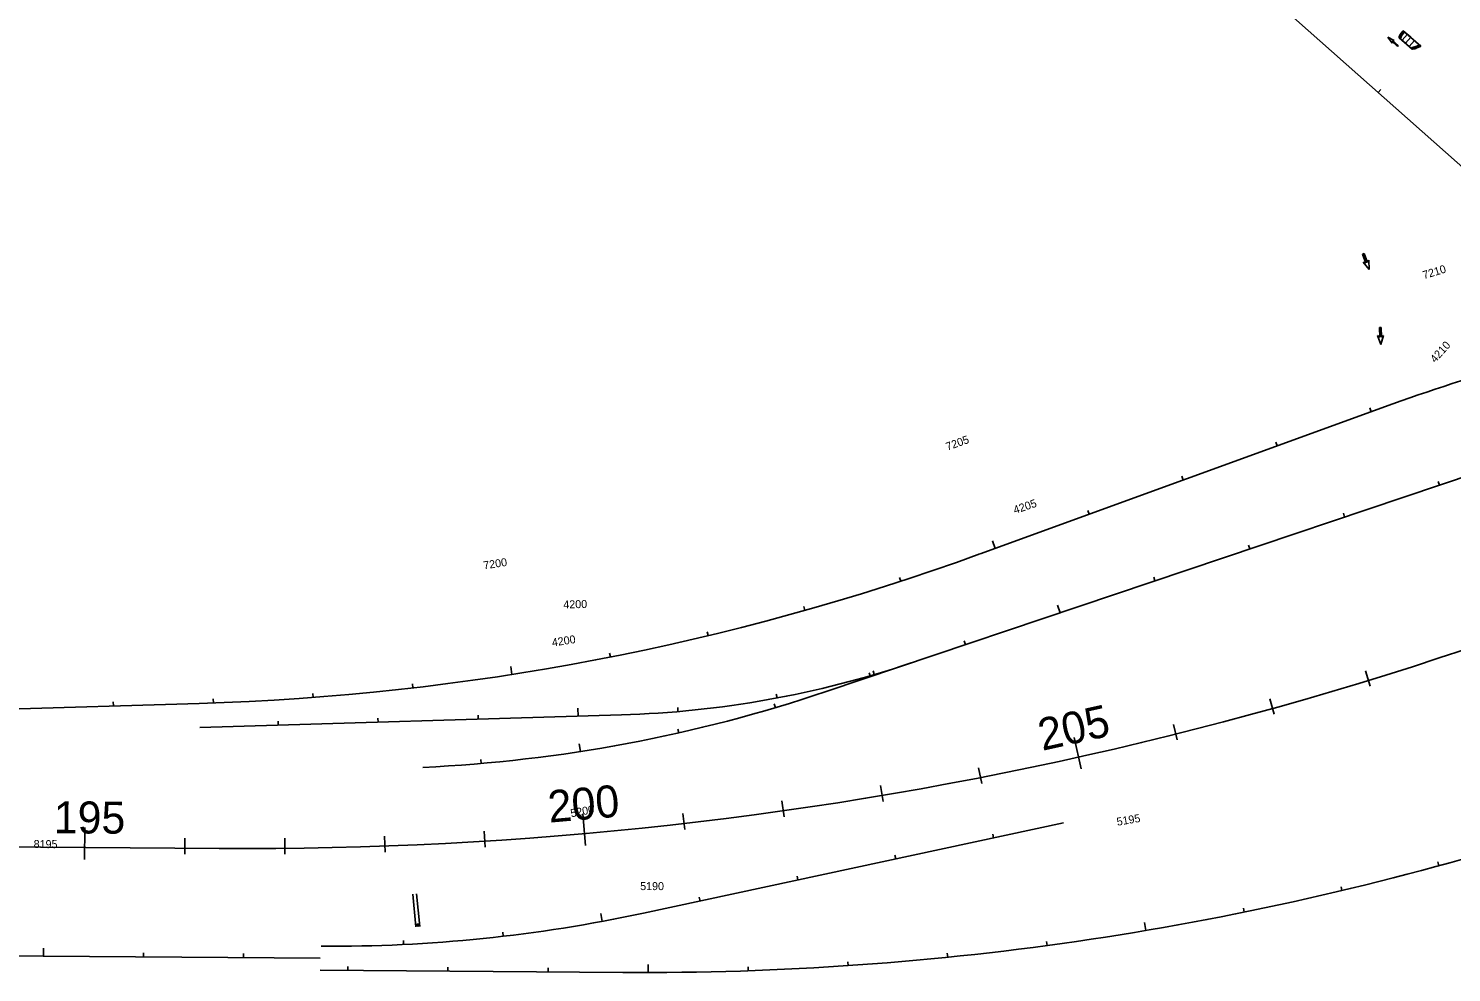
# Model space of a CAD drawing. Extents: x -5665 to 1997148, y 4 to 827579.
# Drawn here: x 1969802 to 1971224, y 802183 to 803127 of the extents above; entities that cross this region are included whole.
import ezdxf

# ---------------------------------------------------------------- set-up
doc = ezdxf.new("R2010")
doc.units = 0
for name, color, linetype in [('RD_EX_BldgApp', 7, 'Continuous'), ('RD_HC_CL_Rel', 7, 'Continuous'), ('RD_HC_Data_Tic_Rel', 7, 'Continuous'), ('RD_HC_TX_Rel_Sta50', 7, 'Continuous'), ('RD_PD_SW', 7, 'Continuous'), ('RD_Sketch8', 7, 'Continuous')]:
    doc.layers.add(name, color=color, linetype=linetype)

msp = doc.modelspace()

# ---------------------------------------------------------------- linework, layer by layer
at = {"layer": 'RD_EX_BldgApp'}
for p, q in [((1970186.2, 802261.1), (1970189.2, 802228.4)), ((1970192.9, 802228.6), (1970189.6, 802261.4))]:
    msp.add_line(p, q, dxfattribs=at)
for points in [[(1970190.5, 802229.4), (1970191.1, 802229.2), (1970191.6, 802229.4), (1970192, 802229.8), (1970192.1, 802230.4), (1970191.8, 802230.9), (1970191.4, 802231.2), (1970190.8, 802231.2), (1970190.3, 802231), (1970190.1, 802230.5), (1970190.1, 802229.9), (1970190.4, 802229.4), (1970190.5, 802229.4)], [(1970190.6, 802229.6), (1970191.1, 802229.4), (1970191.6, 802229.6), (1970191.8, 802230), (1970191.8, 802230.5), (1970191.5, 802230.9), (1970191, 802231.1), (1970190.5, 802230.9), (1970190.3, 802230.4), (1970190.3, 802229.9), (1970190.6, 802229.6)], [(1970190.7, 802229.7), (1970191.2, 802229.6), (1970191.5, 802229.9), (1970191.7, 802230.3), (1970191.5, 802230.7), (1970191.1, 802230.8), (1970190.7, 802230.7), (1970190.5, 802230.4), (1970190.5, 802229.9), (1970190.7, 802229.7)], [(1970190.8, 802229.9), (1970191.2, 802229.9), (1970191.4, 802230.1), (1970191.4, 802230.5), (1970191.1, 802230.6), (1970190.8, 802230.5), (1970190.7, 802230.2), (1970190.8, 802229.9), (1970190.8, 802229.9)], [(1970191, 802230.1), (1970191.2, 802230.1), (1970191.2, 802230.3), (1970191, 802230.4), (1970190.9, 802230.3), (1970191, 802230.1)]]:
    msp.add_lwpolyline(points, dxfattribs=at)
at = {"layer": 'RD_HC_CL_Rel'}
for p, q in [((1970807.3, 803367.7), (1971858, 802435.1)), ((1970753, 802601.3), (1971165.5, 802751.3)), ((1970599.2, 802463.6), (1971248.9, 802682.4)), ((1968911.4, 802420.4), (1969972.6, 802451.8)), ((1969973.3, 802427.8), (1970394.5, 802440.3)), ((1970416.5, 802242), (1970836.6, 802332.4)), ((1969096.7, 802313.5), (1969992.4, 802306.8)), ((1969095.9, 802204.5), (1970093.4, 802197)), ((1970093.3, 802185), (1970396, 802182.8))]:
    msp.add_line(p, q, dxfattribs=at)
for centre, radius, start, end in [((1971678.2, 801341.6), 1500, 99.0087, 109.9838), ((1970020.9, 806126.4), 3819.7, 269.5721, 296.6408), ((1969898.6, 804950.7), 2500, 271.6958, 289.9838), ((1970364.9, 803439.9), 1000, 271.6958, 288.6146), ((1970126.8, 803866.2), 1480, 272.6826, 288.6146), ((1970418.4, 805182.7), 3000, 269.5721, 287.5154), ((1970105.4, 803689), 1480, 269.5721, 282.1339)]:
    msp.add_arc(centre, radius, start, end, dxfattribs=at)
at = {"layer": 'RD_HC_Data_Tic_Rel'}
for p, q in [((1971151, 803062.6), (1971153.7, 803065.6)), ((1971144.1, 802743.5), (1971142.7, 802747.2)), ((1971050.1, 802709.3), (1971048.7, 802713)), ((1970956.1, 802675.1), (1970954.7, 802678.9)), ((1971212.2, 802670), (1971210.9, 802673.8)), ((1970862.1, 802640.9), (1970860.8, 802644.7)), ((1971117.4, 802638.1), (1971116.2, 802641.9)), ((1970768.1, 802606.8), (1970765.4, 802614.3)), ((1971022.7, 802606.2), (1971021.4, 802610)), ((1970673.7, 802573.9), (1970672.5, 802577.7)), ((1970927.9, 802574.3), (1970926.6, 802578.1)), ((1970833.1, 802542.4), (1970830.6, 802549.9)), ((1970578, 802544.8), (1970576.9, 802548.7)), ((1970481.3, 802519.6), (1970480.3, 802523.5)), ((1970738.4, 802510.4), (1970737.1, 802514.2)), ((1970383.6, 802498.2), (1970382.8, 802502.1)), ((1970285.1, 802480.8), (1970283.9, 802488.7)), ((1970643.6, 802478.5), (1970642.3, 802482.3)), ((1970647.3, 802480.6), (1970646.2, 802484.4)), ((1971143.1, 802469), (1971138.4, 802484.3)), ((1970186, 802467.3), (1970185.6, 802471.3)), ((1969886.7, 802449.3), (1969886.6, 802453.3)), ((1969986.7, 802452.3), (1969986.5, 802456.3)), ((1970086.5, 802457.8), (1970086.2, 802461.8)), ((1970548.5, 802447.5), (1970547.4, 802451.4)), ((1970550.2, 802457.2), (1970549.4, 802461.1)), ((1971047, 802440.9), (1971042.7, 802456.3)), ((1970151.3, 802433.1), (1970151.2, 802437.1)), ((1970251.3, 802436.1), (1970251.2, 802440.1)), ((1970351.2, 802439), (1970351, 802447)), ((1970451.1, 802443.6), (1970450.8, 802447.6)), ((1970051.4, 802430.1), (1970051.3, 802434.1)), ((1970451.8, 802422.3), (1970450.9, 802426.2)), ((1970950.2, 802415.3), (1970946.3, 802430.8)), ((1970353.6, 802403.6), (1970352.3, 802411.5)), ((1970854, 802386.3), (1970847.1, 802417.6)), ((1970254.3, 802391.7), (1970254, 802395.6)), ((1970754.7, 802371.7), (1970751.6, 802387.4)), ((1970656.1, 802353.8), (1970653.5, 802369.6)), ((1970557.2, 802338.4), (1970554.9, 802354.3)), ((1970358.7, 802309.6), (1970355.9, 802341.5)), ((1970457.8, 802325.7), (1970456, 802341.6)), ((1969858, 802295.8), (1969858.3, 802327.8)), ((1970258.3, 802308.1), (1970257.3, 802324)), ((1969958.1, 802301), (1969958.2, 802317)), ((1970058.2, 802300.9), (1970058, 802316.9)), ((1970158.3, 802303.1), (1970157.7, 802319.1)), ((1970766.5, 802317.3), (1970765.7, 802321.2)), ((1970668.7, 802296.3), (1970667.9, 802300.2)), ((1971211.7, 802289.5), (1971210.6, 802293.3)), ((1970571, 802275.3), (1970570.1, 802279.2)), ((1971114.8, 802264.6), (1971113.9, 802268.5)), ((1970473.2, 802254.2), (1970472.4, 802258.2)), ((1970375.3, 802233.8), (1970373.9, 802241.7)), ((1971017.2, 802243), (1971016.4, 802247)), ((1970276.4, 802218.9), (1970276, 802222.9)), ((1970918.9, 802224.7), (1970917.5, 802232.6)), ((1970176.8, 802210.7), (1970176.6, 802214.7)), ((1970820, 802209.7), (1970819.5, 802213.6)), ((1969816.9, 802199.1), (1969816.9, 802207.1)), ((1969916.9, 802198.3), (1969916.9, 802202.3)), ((1970016.9, 802197.6), (1970016.9, 802201.6)), ((1970720.7, 802198), (1970720.3, 802201.9)), ((1970121.2, 802184.8), (1970121.2, 802188.8)), ((1970221.2, 802184.1), (1970221.2, 802188.1)), ((1970321.2, 802183.3), (1970321.2, 802187.3)), ((1970421.2, 802182.7), (1970421.2, 802190.7)), ((1970521.2, 802184.4), (1970521.1, 802188.4)), ((1970621.1, 802189.5), (1970620.8, 802193.5))]:
    msp.add_line(p, q, dxfattribs=at)
at = {"layer": 'RD_PD_SW'}
for p, q in [((1971176.1, 803124.4), (1971174, 803122)), ((1971180.2, 803120.9), (1971174.9, 803114.8)), ((1971183.6, 803117.9), (1971176.1, 803124.4)), ((1971176.1, 803124.4), (1971193.8, 803109)), ((1971171.9, 803117.4), (1971185, 803106)), ((1971171.9, 803117.4), (1971178.2, 803111.9)), ((1971183.5, 803117.9), (1971178.2, 803111.9)), ((1971183.5, 803117.9), (1971178.2, 803111.9)), ((1971178.2, 803111.9), (1971183.5, 803117.9)), ((1971178.2, 803111.9), (1971182, 803108.7)), ((1971187.3, 803114.6), (1971182, 803108.6)), ((1971182, 803108.7), (1971187.3, 803114.6)), ((1971187.3, 803114.6), (1971182, 803108.7)), ((1971182, 803108.7), (1971185, 803106)), ((1971187.3, 803114.6), (1971183.6, 803117.9)), ((1971193.8, 803109), (1971187.3, 803114.6)), ((1971189.8, 803107.2), (1971193.8, 803109))]:
    msp.add_line(p, q, dxfattribs=at)
for points in [[(1971173.2, 803120.2), (1971171.9, 803117.4), (1971173.4, 803116.7), (1971175.1, 803120.5)], [(1971183.6, 803117.9), (1971183.5, 803117.9)], [(1971183.5, 803117.9), (1971183.6, 803117.9)], [(1971188.8, 803108.7), (1971184.6, 803107.6), (1971185, 803106), (1971188.5, 803106.9)], [(1971187.3, 803114.6), (1971187.3, 803114.6)], [(1971187.3, 803114.6), (1971187.3, 803114.6)]]:
    msp.add_lwpolyline(points, dxfattribs=at)
for points in [[(1971176.2, 803124.2), (1971172.9, 803120.5), (1971174.2, 803119.4), (1971177.4, 803123.2)], [(1971192.5, 803110.2), (1971187.9, 803108.3), (1971188.5, 803106.8), (1971193.2, 803108.7)]]:
    msp.add_lwpolyline(points, close=True, dxfattribs=at)
for centre, radius in [((1971173, 803119), 0.146), ((1971173, 803119), 0.073), ((1971173.2, 803119.4), 0.146), ((1971173.2, 803119.4), 0.073), ((1971173.4, 803120.5), 0.146), ((1971173.3, 803119.7), 0.146), ((1971173.3, 803119.7), 0.073), ((1971173.4, 803120.5), 0.073), ((1971173.5, 803120.1), 0.146), ((1971173.5, 803118.8), 0.146), ((1971173.5, 803120.1), 0.073), ((1971173.5, 803118.8), 0.073), ((1971173.6, 803120.8), 0.146), ((1971173.6, 803119.1), 0.146), ((1971173.6, 803119.1), 0.073), ((1971173.6, 803120.8), 0.073), ((1971173.8, 803120.2), 0.146), ((1971173.8, 803119.5), 0.146), ((1971173.8, 803120.2), 0.073), ((1971173.8, 803119.5), 0.073), ((1971173.9, 803121.1), 0.073), ((1971173.9, 803121.1), 0.146), ((1971174, 803120.5), 0.146), ((1971174, 803120.5), 0.073), ((1971174.1, 803118.9), 0.146), ((1971174.2, 803121.4), 0.146), ((1971174.1, 803119.8), 0.146), ((1971174.1, 803118.9), 0.073), ((1971174.2, 803121.4), 0.073), ((1971174.3, 803120.8), 0.146), ((1971174.1, 803119.8), 0.073), ((1971174.2, 803119.3), 0.146), ((1971174.3, 803120.8), 0.073), ((1971174.4, 803120.1), 0.146), ((1971174.2, 803119.3), 0.073), ((1971174.4, 803121.7), 0.146), ((1971174.4, 803120.1), 0.073), ((1971174.4, 803119.7), 0.146), ((1971174.4, 803119.7), 0.073), ((1971174.4, 803121.7), 0.073), ((1971174.5, 803121.1), 0.146), ((1971174.7, 803122), 0.146), ((1971174.5, 803121.1), 0.073), ((1971174.7, 803120.4), 0.146), ((1971174.7, 803122), 0.073), ((1971174.7, 803120.4), 0.073), ((1971174.8, 803121.4), 0.146), ((1971174.8, 803121.4), 0.073), ((1971174.9, 803122.3), 0.146), ((1971174.9, 803120.7), 0.146), ((1971174.9, 803120.7), 0.073), ((1971174.9, 803122.3), 0.073), ((1971175.1, 803121.7), 0.146), ((1971175.1, 803121.7), 0.073), ((1971175.2, 803121), 0.146), ((1971175.2, 803122.6), 0.073), ((1971175.2, 803122.6), 0.146), ((1971175.2, 803121), 0.073), ((1971175.3, 803122), 0.146), ((1971175.5, 803122.9), 0.146), ((1971175.3, 803122), 0.073), ((1971175.4, 803121.3), 0.146), ((1971175.5, 803122.9), 0.073), ((1971175.6, 803122.3), 0.146), ((1971175.4, 803121.3), 0.073), ((1971175.6, 803122.3), 0.073), ((1971175.7, 803123.2), 0.146), ((1971175.7, 803121.6), 0.146), ((1971175.7, 803121.6), 0.073), ((1971175.7, 803123.2), 0.073), ((1971175.9, 803122.6), 0.146), ((1971175.9, 803122.6), 0.073), ((1971176, 803121.9), 0.146), ((1971176, 803123.5), 0.073), ((1971176, 803123.5), 0.146), ((1971176, 803121.9), 0.073), ((1971176.1, 803122.9), 0.146), ((1971176.1, 803122.9), 0.073), ((1971176.3, 803123.8), 0.146), ((1971176.2, 803122.2), 0.146), ((1971176.3, 803123.8), 0.073), ((1971176.4, 803123.2), 0.146), ((1971176.2, 803122.2), 0.073), ((1971176.4, 803123.2), 0.073), ((1971176.5, 803122.5), 0.146), ((1971176.5, 803122.5), 0.073), ((1971176.6, 803123.5), 0.146), ((1971176.6, 803123.5), 0.073), ((1971176.8, 803122.8), 0.146), ((1971176.8, 803122.8), 0.073), ((1971177, 803123.1), 0.146), ((1971177, 803123.1), 0.073), ((1971172.3, 803117.5), 0.146), ((1971172.3, 803117.5), 0.073), ((1971172.5, 803117.9), 0.073), ((1971172.5, 803117.9), 0.146), ((1971172.7, 803118.3), 0.146), ((1971172.7, 803118.3), 0.073), ((1971172.8, 803117.3), 0.146), ((1971172.8, 803118.6), 0.146), ((1971172.8, 803117.3), 0.073), ((1971172.8, 803118.6), 0.073), ((1971173, 803117.7), 0.146), ((1971173, 803117.7), 0.073), ((1971173.1, 803118.1), 0.146), ((1971173.3, 803118.4), 0.146), ((1971173.1, 803118.1), 0.073), ((1971173.2, 803117.1), 0.146), ((1971173.3, 803118.4), 0.073), ((1971173.2, 803117.1), 0.073), ((1971173.4, 803117.5), 0.073), ((1971173.4, 803117.5), 0.146), ((1971173.6, 803117.8), 0.146), ((1971173.6, 803117.8), 0.073), ((1971173.7, 803118.2), 0.146), ((1971173.7, 803118.2), 0.073), ((1971173.9, 803118.6), 0.146), ((1971173.9, 803118.6), 0.073), ((1971185, 803107.4), 0.146), ((1971185, 803107.4), 0.073), ((1971185.1, 803106.9), 0.073), ((1971185.1, 803106.9), 0.146), ((1971185.2, 803106.4), 0.146), ((1971185.4, 803107.5), 0.146), ((1971185.2, 803106.4), 0.073), ((1971185.4, 803107.5), 0.073), ((1971185.5, 803107), 0.073), ((1971185.5, 803107), 0.146), ((1971185.6, 803106.5), 0.073), ((1971185.6, 803106.5), 0.146), ((1971185.8, 803107.6), 0.146), ((1971185.8, 803107.6), 0.073), ((1971185.9, 803107.1), 0.146), ((1971185.9, 803107.1), 0.073), ((1971186, 803106.6), 0.073), ((1971186, 803106.6), 0.146), ((1971186.1, 803107.7), 0.146), ((1971186.1, 803107.7), 0.073), ((1971186.3, 803107.2), 0.146), ((1971186.3, 803107.2), 0.073), ((1971186.4, 803106.7), 0.146), ((1971186.4, 803106.7), 0.073), ((1971186.5, 803107.8), 0.146), ((1971186.5, 803107.8), 0.073), ((1971186.7, 803107.3), 0.146), ((1971186.7, 803107.3), 0.073), ((1971186.8, 803106.8), 0.146), ((1971186.8, 803106.8), 0.073), ((1971186.9, 803107.9), 0.146), ((1971186.9, 803107.9), 0.073), ((1971187, 803107.4), 0.146), ((1971187, 803107.4), 0.073), ((1971187.2, 803106.9), 0.146), ((1971187.2, 803106.9), 0.073), ((1971187.3, 803108), 0.146), ((1971187.3, 803108), 0.073), ((1971187.4, 803107.5), 0.146), ((1971187.4, 803107.5), 0.073), ((1971187.6, 803107), 0.146), ((1971187.7, 803108.1), 0.146), ((1971187.6, 803107), 0.073), ((1971187.7, 803108.1), 0.073), ((1971187.8, 803107.6), 0.073), ((1971187.8, 803107.6), 0.146), ((1971187.9, 803107.1), 0.146), ((1971187.9, 803107.1), 0.073), ((1971188.3, 803108.2), 0.146), ((1971188.3, 803108.2), 0.073), ((1971188.5, 803107.7), 0.073), ((1971188.5, 803107.7), 0.146), ((1971188.7, 803108.3), 0.146), ((1971188.7, 803108.3), 0.073), ((1971188.7, 803107.2), 0.146), ((1971188.7, 803107.2), 0.073), ((1971188.9, 803107.8), 0.146), ((1971188.9, 803107.8), 0.073), ((1971189.1, 803108.5), 0.146), ((1971189.1, 803107.4), 0.146), ((1971189.1, 803108.5), 0.073), ((1971189.1, 803107.4), 0.073), ((1971189.3, 803108), 0.146), ((1971189.3, 803108), 0.073), ((1971189.4, 803108.6), 0.146), ((1971189.4, 803107.5), 0.146), ((1971189.4, 803108.6), 0.073), ((1971189.4, 803107.5), 0.073), ((1971189.6, 803108.1), 0.146), ((1971189.6, 803108.1), 0.073), ((1971189.8, 803108.8), 0.146), ((1971189.8, 803108.8), 0.073), ((1971189.8, 803107.7), 0.146), ((1971189.8, 803107.7), 0.073), ((1971190, 803108.3), 0.073), ((1971190, 803108.3), 0.146), ((1971190.2, 803108.9), 0.146), ((1971190.2, 803107.8), 0.146), ((1971190.2, 803108.9), 0.073), ((1971190.2, 803107.8), 0.073), ((1971190.4, 803108.4), 0.146), ((1971190.4, 803108.4), 0.073), ((1971190.5, 803109.1), 0.146), ((1971190.6, 803108), 0.146), ((1971190.5, 803109.1), 0.073), ((1971190.6, 803108), 0.073), ((1971190.7, 803108.6), 0.146), ((1971190.7, 803108.6), 0.073), ((1971190.9, 803109.2), 0.146), ((1971190.9, 803109.2), 0.073), ((1971190.9, 803108.1), 0.146), ((1971190.9, 803108.1), 0.073), ((1971191.1, 803108.7), 0.146), ((1971191.1, 803108.7), 0.073), ((1971191.3, 803109.4), 0.146), ((1971191.3, 803109.4), 0.073), ((1971191.3, 803108.3), 0.073), ((1971191.3, 803108.3), 0.146), ((1971191.5, 803108.9), 0.146), ((1971191.5, 803108.9), 0.073), ((1971191.7, 803109.5), 0.146), ((1971191.7, 803108.4), 0.146), ((1971191.7, 803109.5), 0.073), ((1971191.7, 803108.4), 0.073), ((1971191.9, 803109), 0.146), ((1971191.9, 803109), 0.073), ((1971192, 803109.7), 0.146), ((1971192, 803108.6), 0.146), ((1971192, 803109.7), 0.073), ((1971192, 803108.6), 0.073), ((1971192.2, 803109.2), 0.073), ((1971192.2, 803109.2), 0.146), ((1971192.4, 803109.8), 0.146), ((1971192.4, 803109.8), 0.073), ((1971192.4, 803108.7), 0.146), ((1971192.4, 803108.7), 0.073), ((1971192.6, 803109.4), 0.146), ((1971192.6, 803109.4), 0.073), ((1971192.8, 803108.9), 0.146), ((1971192.8, 803108.9), 0.073)]:
    msp.add_circle(centre, radius, dxfattribs=at)
for centre, radius, start, end in [((1971180.3, 803116.3), 8.5, 138.2368, 172.4191), ((1971184.3, 803119.5), 13.5, 273.2263, 294.0804)]:
    msp.add_arc(centre, radius, start, end, dxfattribs=at)
at = {"layer": 'RD_Sketch8'}
for p, q in [((1971164.9, 803112.1), (1971160.7, 803118.1)), ((1971160.7, 803118.1), (1971167.1, 803114.6)), ((1971170.4, 803108.7), (1971164.7, 803113.8)), ((1971164.7, 803113.8), (1971164.9, 803112.1)), ((1971167.1, 803114.6), (1971165.4, 803114.6)), ((1971165.4, 803114.6), (1971171.1, 803109.5)), ((1971171.1, 803109.5), (1971170.4, 803108.7)), ((1971135.2, 802901), (1971136.9, 802901.6)), ((1971138.6, 802892), (1971135.2, 802901)), ((1971142, 802885.5), (1971136.1, 802892.9)), ((1971136.1, 802892.9), (1971138.6, 802892)), ((1971136.9, 802901.6), (1971140.3, 802892.6)), ((1971140.3, 802892.6), (1971141.6, 802894.9)), ((1971141.6, 802894.9), (1971142, 802885.5)), ((1971152.3, 802827.5), (1971154.1, 802827.6)), ((1971152.5, 802817.9), (1971152.3, 802827.5)), ((1971154.1, 802827.6), (1971154.3, 802818)), ((1971153.6, 802810.6), (1971150.4, 802819.6)), ((1971150.4, 802819.6), (1971152.5, 802817.9)), ((1971156.3, 802819.7), (1971153.6, 802810.6)), ((1971154.3, 802818), (1971156.3, 802819.7))]:
    msp.add_line(p, q, dxfattribs=at)

# ---------------------------------------------------------------- texts
at = {"layer": 'RD_HC_TX_Rel_Sta50'}
for s, height, rotation, p in [('7210', 8, 17.0374, (1971196.8, 802875.9)), ('4210', 8, 48.2915, (1971208.1, 802791.8)), ('7205', 8, 19.9838, (1970720.5, 802704.4)), ('4205', 8, 18.6146, (1970787.9, 802641.1)), ('7200', 8, 8.8933, (1970257.2, 802585.7)), ('4200', 8, 1.6958, (1970336.6, 802546.6)), ('4200', 8, 8.8137, (1970325.7, 802508.6)), ('205', 32, 12.5582, (1970815.2, 802404.3)), ('200', 32, 5.0582, (1970322.5, 802332.5)), ('195', 32, 359.5721, (1969827.1, 802322)), ('5200', 8, 10.5095, (1970344.4, 802337.9)), ('5195', 8, 9.6029, (1970890.3, 802329.4)), ('8195', 8, 359.5721, (1969807, 802307.2)), ('5190', 8, 0.0536, (1970413.3, 802265.1))]:
    msp.add_text(s, height=height, rotation=rotation, dxfattribs=at).set_placement(p)

doc.saveas('drawing.dxf')
